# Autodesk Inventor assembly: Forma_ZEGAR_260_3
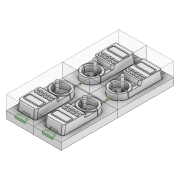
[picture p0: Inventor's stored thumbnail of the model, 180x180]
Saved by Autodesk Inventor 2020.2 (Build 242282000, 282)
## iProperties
Created: 2015-01
Part Number: Forma_ZEGAR_260_3
Document SubType Name: Assembly
Designer: F.Stasiak
Catalog Web Link: www.expertbooks.pl
Manager: www.cadconsulting.pl
Company: Fabian Stasiak CAD Consulting
Author: F.Stasiak
Subject: Zbiór ćwiczeń. Autodesk Inventor 2020. Kurs Professional
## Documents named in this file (3)
- C:\2020_Kurs_Professional\R6 Formy\Forma_ZEGAR_260_3.iam
- C:\2020_Kurs_Professional\R6 Formy\Komponenty\Forma_ZEGAR_260_3_ZEGAR_260_LY.iam
- C:\2020_Kurs_Professional\R6 Formy\Komponenty\Forma_ZEGAR_260_3_RG.ipt
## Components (2 placed, 2 different names)
1. Forma_ZEGAR_260_3_ZEGAR_260_LY:1 [sub-assembly] — Równoległy:1, Równoległy:2, Równoległy:3
2. Forma_ZEGAR_260_3_RG:1 — Równoległy:4, Równoległy:5, Równoległy:6
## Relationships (6: Flush 6)
- Równoległy:1 [Flush]: Forma_ZEGAR_260_3_ZEGAR_260_LY:1
- Równoległy:2 [Flush]: Forma_ZEGAR_260_3_ZEGAR_260_LY:1
- Równoległy:3 [Flush]: Forma_ZEGAR_260_3_ZEGAR_260_LY:1
- Równoległy:4 [Flush]: Forma_ZEGAR_260_3_RG:1
- Równoległy:5 [Flush]: Forma_ZEGAR_260_3_RG:1
- Równoległy:6 [Flush]: Forma_ZEGAR_260_3_RG:1
